(* Logix 5000 project; controller SmartVs_V02 1769-L33ERM rev 32.11; software revision 32.01 *)

TASK MainTask (continuous, watchdog 500 ms) : MainProgram

MODULES
   Local : 1769-L33ERM (Compact 0, rev 32.11)
END_MODULES

TYPE SKT_Accept_Response :
STRUCT
   Instance : DINT;
   Addr : SKT_Address;
END_STRUCT
END_TYPE

TYPE SKT_Address :
STRUCT
   Family : INT;   // Address Family Must be 2
   Port : INT;   // Port Number
   Addr : SINT[4];   // IP Address
END_STRUCT
END_TYPE

TYPE SKT_Create_Parameters :
STRUCT
   Type : DINT;   // 1 - TCP 2- UPD
   Addr : SKT_Address;
END_STRUCT
END_TYPE

TYPE SKT_DATA_CLIENT :
STRUCT
   Timeout : DINT;
   Create_Source : SKT_Create_Parameters;
   Instance : DINT;
   Connect_Source : SKT_OpenConnection_Parameters;
   Read_Source : SKT_Read_Parameters;
   Read_Response : SKT_Read_Response;
   Write_Source : SKT_Write_Parameters;
   Write_SizeSent : DINT;
END_STRUCT
END_TYPE

TYPE SKT_DATA_SERVER :
STRUCT
   Timeout : DINT;
   Create_Source : SKT_Create_Parameters;
   Accept_Socket_Instance : DINT;
   Accept_Timeout : DINT;
   Accept_Response : SKT_Accept_Response;
   Read_Source : SKT_Read_Parameters;
   Read_Response : SKT_Read_Response;
   Write_Source : SKT_Write_Parameters;
   Write_SizeSent : DINT;
   Server_Socket_Instance : DINT;
END_STRUCT
END_TYPE

TYPE SKT_DATA_UDP :
STRUCT
   Timeout : DINT;
   Create_Source : SKT_Create_Parameters;
   Connect_Source : SKT_OpenConnection_Parameters;
   Read_Source : SKT_Read_Parameters;
   Write_Source : SKT_Write_Parameters;
   Instance : DINT;
   Read_Response : SKT_Read_Response;
   Write_SizeSent : DINT;
END_STRUCT
END_TYPE

TYPE SKT_OpenConnection_Parameters :
STRUCT
   Timeout : DINT;
   DestAddr : STRING;
END_STRUCT
END_TYPE

TYPE SKT_Read_Parameters :
STRUCT
   Timeout : DINT;
   BufLen : DINT;
END_STRUCT
END_TYPE

TYPE SKT_Read_Response :
STRUCT
   FromAddr : SKT_Address;
   Buffer : STR_480;
END_STRUCT
END_TYPE

TYPE SKT_Write_Parameters :
STRUCT
   Timeout : DINT;
   ToAddr : SKT_Address;
   Buffer : STR_480;
END_STRUCT
END_TYPE

TYPE STR_480 :   // string type
STRUCT
   LEN : DINT;
   DATA : SINT[480];
END_STRUCT
END_TYPE

TYPE UDT_SmartVs :
STRUCT
   i_xEnable : BOOL;   // Enable Socket Creation and Connection
   i_xWrite : BOOL;   // Write Data Rq
   iq_xResetFB : BOOL;   // Delete all open Sockets
   i_xChangeJob : BOOL;   // Load Job-a number between 1-24
   i_sJobData : STRING;   // Job Data
   o_xEnabled : BOOL;   // Socket created and connected
   o_sJobResult : STRING;   // Job Result String (Done/Fail)
   o_iErrorCode : INT;   // FB Error code
   iState : INT;
   i_iJobData : INT;   // Number of job to load
   sFeedback : STRING;   // Feedback string-from server to client
   sFormatData : STRING;   // Number of job in String Format
   o_xError : BOOL;   // Error
   o_iError : INT;   // FB diagnostic Error code
   diStringlen : DINT;   // String lenght according to the format number
END_STRUCT
END_TYPE

ADD_ON_INSTRUCTION SKT_AOI_TCP_CLIENT   (* revision 1.0, ExecutePrescan *)
VAR_IN_OUT
   Client_Data : SKT_DATA_CLIENT; {required}   // This tags holds all the data used by the messages
END_VAR
VAR_INPUT
   Enable_Socket : BOOL; {visible}   // Set by user to enable or disable socket
   Stop_On_Error : BOOL; {visible}   // If any message errors, then delete socket and stop
END_VAR
VAR_IN_OUT
   Create_MSG : MESSAGE; {required}   // Create socket
   Connect_MSG : MESSAGE; {required}   // Connect socket to server.
   Read_MSG : MESSAGE; {required}   // Message to tell socket to return any data it has recieved
   Write_MSG : MESSAGE; {required}   // Write socket message
   Delete_MSG : MESSAGE; {required}   // Delete socket
END_VAR
VAR_OUTPUT
   ENABLED : BOOL; {access Read Only, visible}   // Socket not currently open
   CONNECTING : BOOL; {access Read Only, visible}   // Trying to connect to Server.
   OPEN : BOOL; {access Read Only, visible}   // Socket connection Open
   READ : BOOL; {access Read Only, visible}   // New Data Ready - Set by AOI when a string is received, cleared by user to acknowledge
   WRITE : BOOL; {access Read Only, visible}   // Set this bit to Write Data
   ERROR : BOOL; {access Read Only, visible}   // A message had an Error
END_VAR
VAR
   lastport : DINT; {access None}
   xEnable : DINT; {access None}
   xWrite : DINT; {access None}
   xRead : DINT; {access None}
   State : DINT := 60;   // Current state
END_VAR

ROUTINE Logic   (* ladder *)
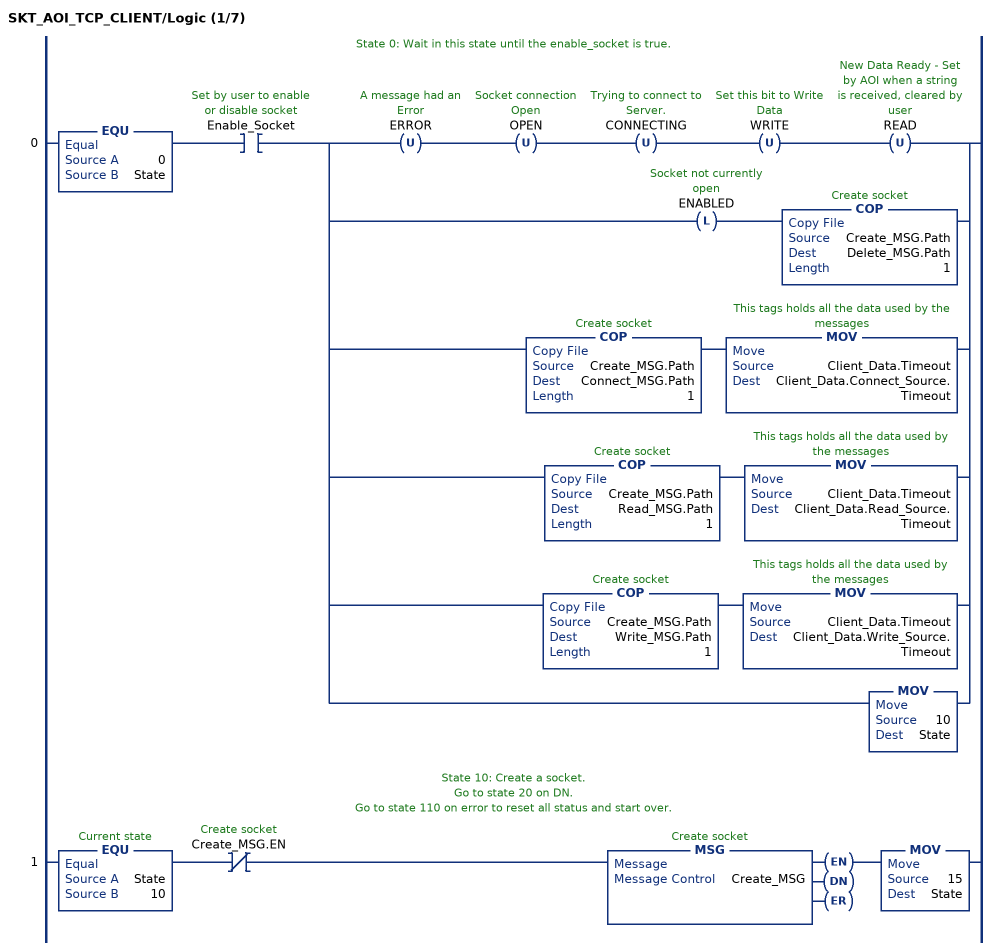
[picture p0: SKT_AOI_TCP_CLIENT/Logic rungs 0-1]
   // State 0: Wait in this state until the enable_socket is true.
   0: EQU(0,State)XIC(Enable_Socket)[OTU(ERROR) OTU(OPEN) OTU(CONNECTING) OTU(WRITE) OTU(READ) ,OTL(ENABLED) COP(Create_MSG.Path,Delete_MSG.Path,1) ,COP(Create_MSG.Path,Connect_MSG.Path,1) MOV(Client_Data.Timeout,Client_Data.Connect_Source.Timeout) ,COP(Create_MSG.Path,Read_MSG.Path,1) MOV(Client_Data.Timeout,Client_Data.Read_Source.Timeout) ,COP(Create_MSG.Path,Write_MSG.Path,1) MOV(Client_Data.Timeout,Client_Data.Write_Source.Timeout) ,MOV(10,State) ];
   // State 10: Create a socket.
   // Go to state 20 on DN.
   // Go to state 110 on error to reset all status and start over.
   1: EQU(State,10)XIO(Create_MSG.EN)MSG(Create_MSG)MOV(15,State);
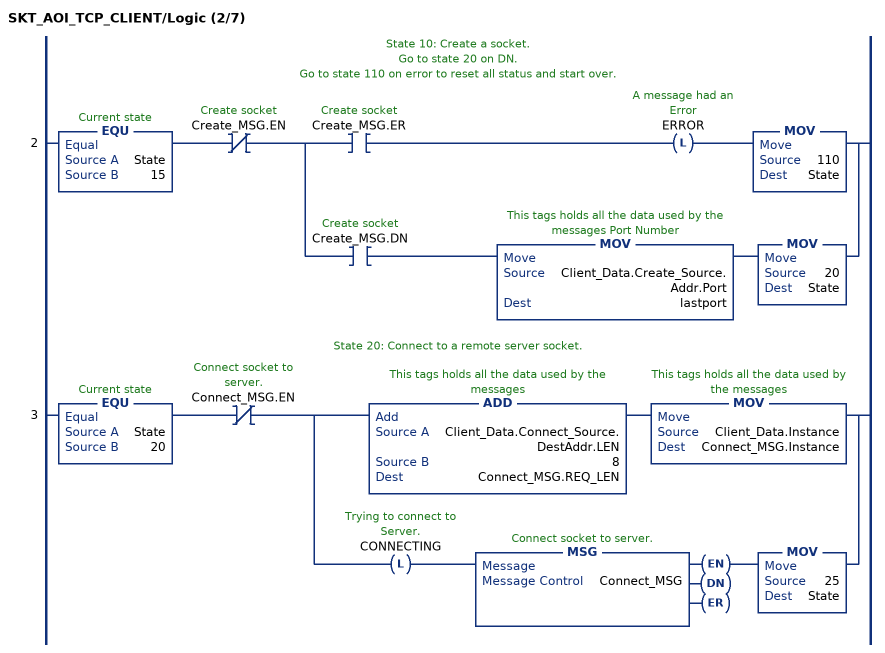
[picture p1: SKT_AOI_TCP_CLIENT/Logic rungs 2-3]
   // State 10: Create a socket.
   // Go to state 20 on DN.
   // Go to state 110 on error to reset all status and start over.
   2: EQU(State,15)XIO(Create_MSG.EN)[XIC(Create_MSG.ER) OTL(ERROR) MOV(110,State) ,XIC(Create_MSG.DN) MOV(Client_Data.Create_Source.Addr.Port,lastport) MOV(20,State) ];
   // State 20: Connect to a remote server socket.
   3: EQU(State,20)XIO(Connect_MSG.EN)[ADD(Client_Data.Connect_Source.DestAddr.LEN,8,Connect_MSG.REQ_LEN) MOV(Client_Data.Instance,Connect_MSG.Instance) ,OTL(CONNECTING) MSG(Connect_MSG) MOV(25,State) ];
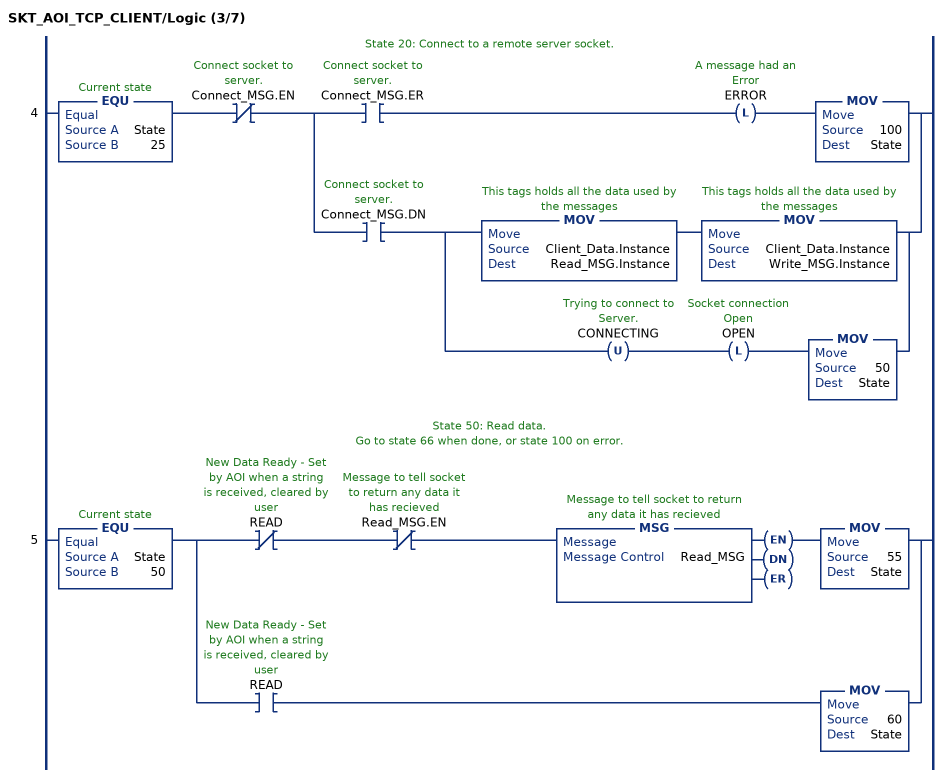
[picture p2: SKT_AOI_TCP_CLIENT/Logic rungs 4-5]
   // State 20: Connect to a remote server socket.
   4: EQU(State,25)XIO(Connect_MSG.EN)[XIC(Connect_MSG.ER) OTL(ERROR) MOV(100,State) ,XIC(Connect_MSG.DN) [MOV(Client_Data.Instance,Read_MSG.Instance) MOV(Client_Data.Instance,Write_MSG.Instance) ,OTU(CONNECTING) OTL(OPEN) MOV(50,State) ] ];
   // State 50: Read data.
   // Go to state 66 when done, or state 100 on error.
   5: EQU(State,50)[XIO(READ) XIO(Read_MSG.EN) MSG(Read_MSG) MOV(55,State) ,XIC(READ) MOV(60,State) ];
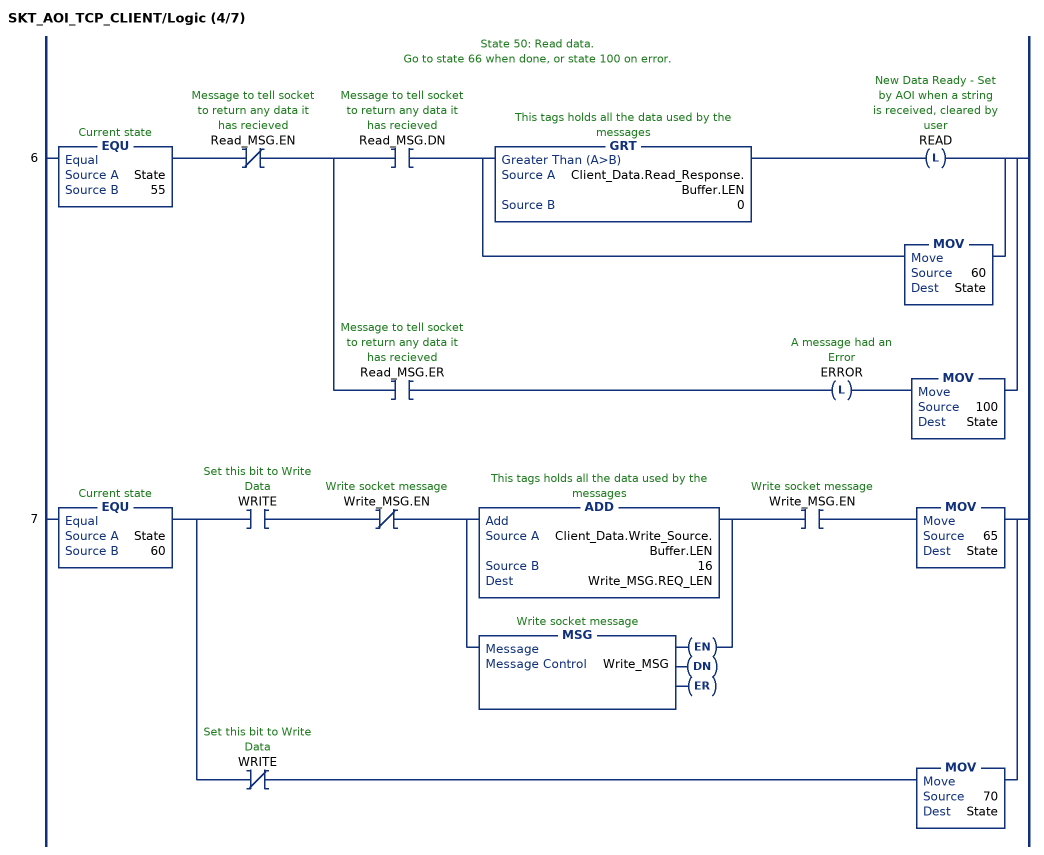
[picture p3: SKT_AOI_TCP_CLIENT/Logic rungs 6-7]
   // State 50: Read data.
   // Go to state 66 when done, or state 100 on error.
   6: EQU(State,55)XIO(Read_MSG.EN)[XIC(Read_MSG.DN) [GRT(Client_Data.Read_Response.Buffer.LEN,0) OTL(READ) ,MOV(60,State) ] ,XIC(Read_MSG.ER) OTL(ERROR) MOV(100,State) ];
   7: EQU(State,60)[XIC(WRITE) XIO(Write_MSG.EN) [ADD(Client_Data.Write_Source.Buffer.LEN,16,Write_MSG.REQ_LEN) ,MSG(Write_MSG) ] XIC(Write_MSG.EN) MOV(65,State) ,XIO(WRITE) MOV(70,State) ];
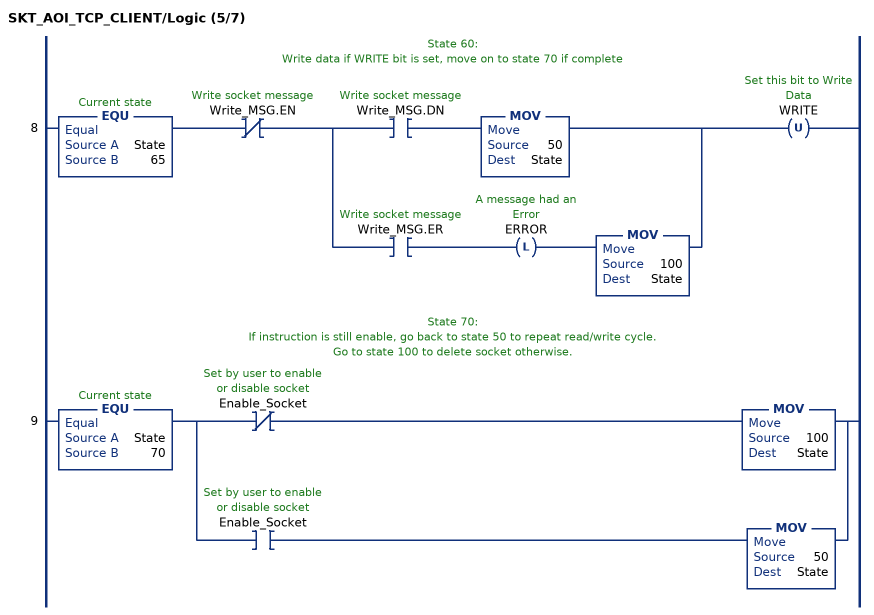
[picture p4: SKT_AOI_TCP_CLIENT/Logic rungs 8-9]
   // State 60:
   // Write data if WRITE bit is set, move on to state 70 if complete
   8: EQU(State,65)XIO(Write_MSG.EN)[XIC(Write_MSG.DN) MOV(50,State) ,XIC(Write_MSG.ER) OTL(ERROR) MOV(100,State) ]OTU(WRITE);
   // State 70:
   // If instruction is still enable, go back to state 50 to repeat read/write cycle.
   // Go to state 100 to delete socket otherwise.
   9: EQU(State,70)[XIO(Enable_Socket) MOV(100,State) ,XIC(Enable_Socket) MOV(50,State) ];
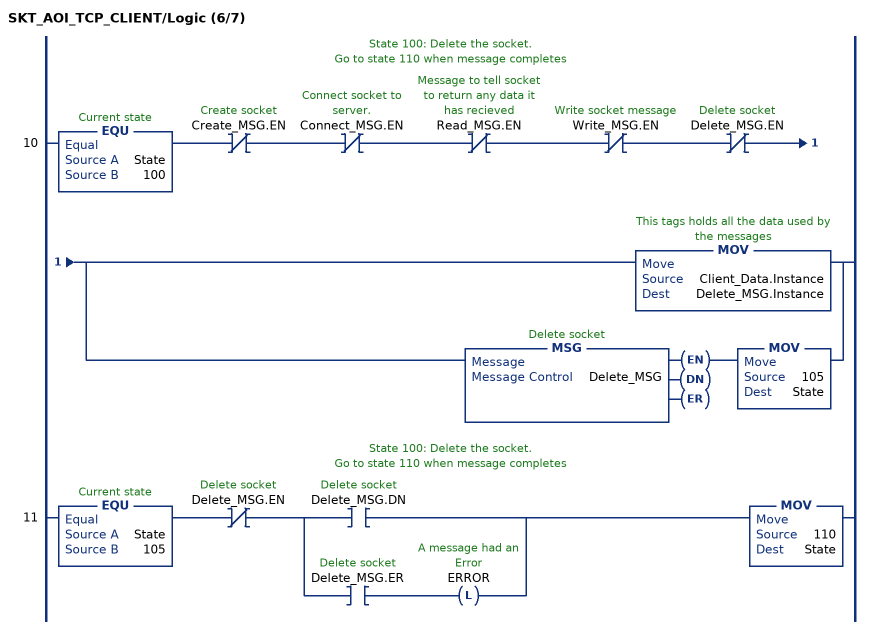
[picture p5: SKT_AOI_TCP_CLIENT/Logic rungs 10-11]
   // State 100: Delete the socket.
   // Go to state 110 when message completes
   10: EQU(State,100)XIO(Create_MSG.EN)XIO(Connect_MSG.EN)XIO(Read_MSG.EN)XIO(Write_MSG.EN)XIO(Delete_MSG.EN)[MOV(Client_Data.Instance,Delete_MSG.Instance) ,MSG(Delete_MSG) MOV(105,State) ];
   // State 100: Delete the socket.
   // Go to state 110 when message completes
   11: EQU(State,105)XIO(Delete_MSG.EN)[XIC(Delete_MSG.DN) ,XIC(Delete_MSG.ER) OTL(ERROR) ]MOV(110,State);
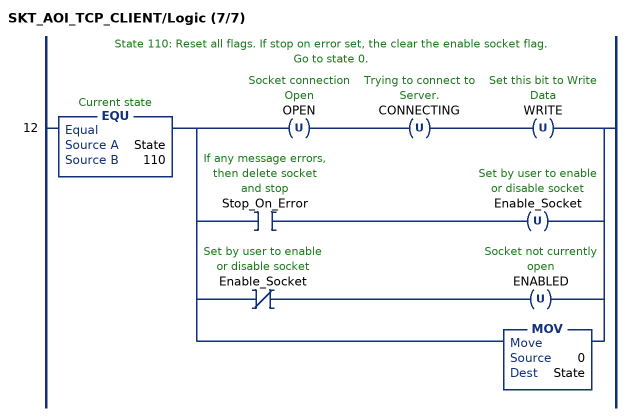
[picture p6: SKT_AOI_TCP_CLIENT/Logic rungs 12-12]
   // State 110: Reset all flags. If stop on error set, the clear the enable socket flag.
   // Go to state 0.
   12: EQU(State,110)[OTU(OPEN) OTU(CONNECTING) OTU(WRITE) ,XIC(Stop_On_Error) OTU(Enable_Socket) ,XIO(Enable_Socket) OTU(ENABLED) ,MOV(0,State) ];
END_ROUTINE

ROUTINE Prescan   (* ladder *)
// Prescan
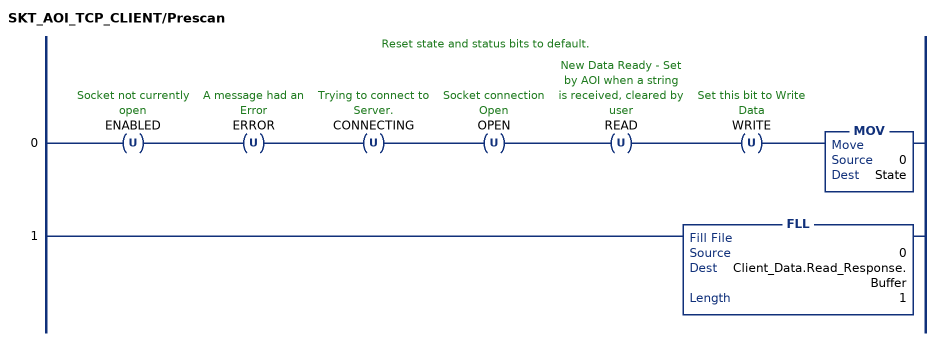
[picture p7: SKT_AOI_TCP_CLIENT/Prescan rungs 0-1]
   // Reset state and status bits to default.
   0: OTU(ENABLED)OTU(ERROR)OTU(CONNECTING)OTU(OPEN)OTU(READ)OTU(WRITE)MOV(0,State);
   1: FLL(0,Client_Data.Read_Response.Buffer,1);
END_ROUTINE
END_ADD_ON_INSTRUCTION

ADD_ON_INSTRUCTION SKT_AOI_TCP_SERVER   (* revision 1.0, ExecutePrescan *)
VAR_IN_OUT
   Server_Data : SKT_DATA_SERVER; {required}   // This tag is used to hold source and dest tags of all socket messages.
        .Read_Response.Buffer.LEN   // Tag used to hold data for messages
END_VAR
VAR_INPUT
   Enable_Socket : BOOL; {visible}   // Set by user to enable or disable socket
   Stop_on_Error : BOOL; {visible}   // Stop on any socket errors
END_VAR
VAR_IN_OUT
   Create_MSG : MESSAGE; {required}   // Create socket
   Accept_MSG : MESSAGE; {required}   // Listen for incoming connection.
   Read_MSG : MESSAGE; {required}   // Read Socket Message
   Write_MSG : MESSAGE; {required}   // Write socket message
   Delete_MSG : MESSAGE; {required}   // Delete socket
END_VAR
VAR_OUTPUT
   ENABLED : BOOL; {access Read Only, visible}
   LISTENING : BOOL; {access Read Only, visible}   // Socket is listening for incoming connection
   OPEN : BOOL; {access Read Only, visible}   // Socket Connection Open
   READ : BOOL; {access Read Only, visible}   // Data in Read buffer
   WRITE : BOOL; {access Read Only, visible}   // Set to send data.
   ERROR : BOOL; {access Read Only, visible}   // At least one message has an error
END_VAR
VAR
   State : DINT := 20;   // Current state
   DELETE_Socket : BOOL; {access None}
   DELETE_Running : BOOL; {access None}
END_VAR

ROUTINE Logic   (* ladder *)
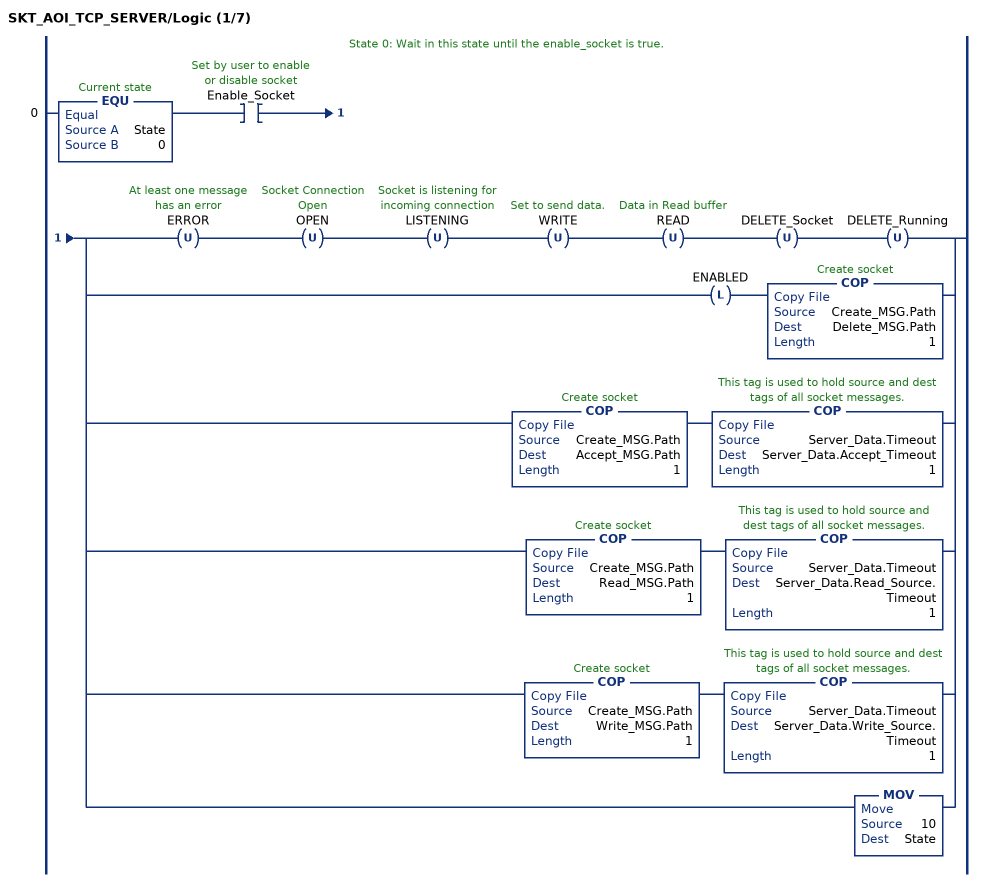
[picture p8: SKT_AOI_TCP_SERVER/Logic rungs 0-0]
   // State 0: Wait in this state until the enable_socket is true.
   0: EQU(State,0)XIC(Enable_Socket)[OTU(ERROR) OTU(OPEN) OTU(LISTENING) OTU(WRITE) OTU(READ) OTU(DELETE_Socket) OTU(DELETE_Running) ,OTL(ENABLED) COP(Create_MSG.Path,Delete_MSG.Path,1) ,COP(Create_MSG.Path,Accept_MSG.Path,1) COP(Server_Data.Timeout,Server_Data.Accept_Timeout,1) ,COP(Create_MSG.Path,Read_MSG.Path,1) COP(Server_Data.Timeout,Server_Data.Read_Source.Timeout,1) ,COP(Create_MSG.Path,Write_MSG.Path,1) COP(Server_Data.Timeout,Server_Data.Write_Source.Timeout,1) ,MOV(10,State) ];
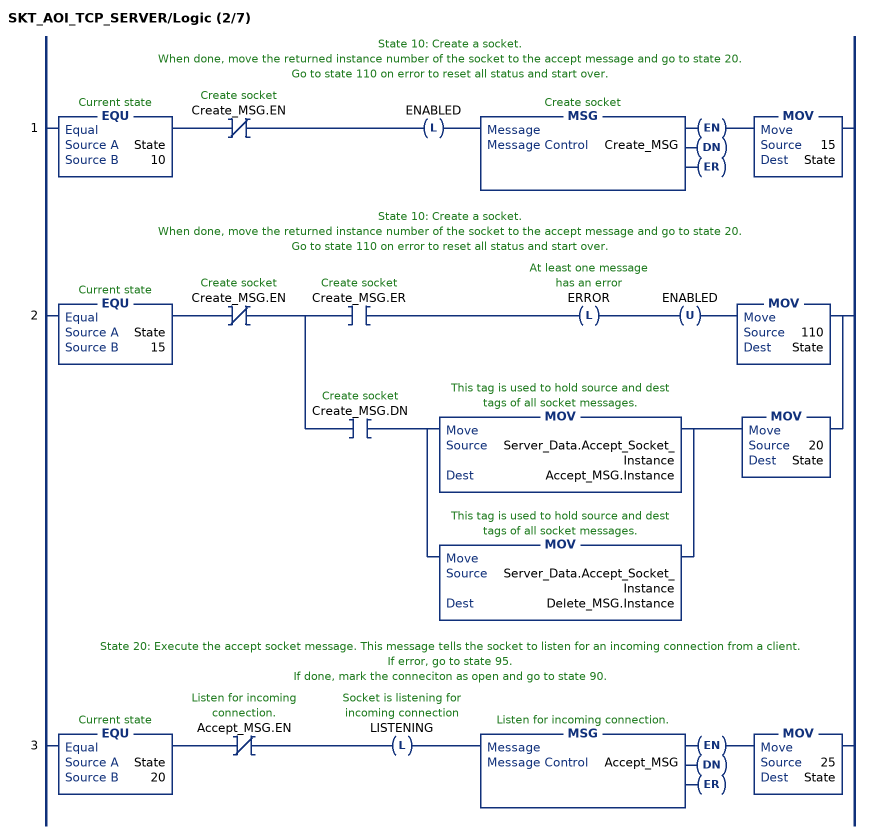
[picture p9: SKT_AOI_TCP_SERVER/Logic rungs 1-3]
   // State 10: Create a socket.
   // When done, move the returned instance number of the socket to the accept message and go to state 20.
   // Go to state 110 on error to reset all status and start over.
   1: EQU(State,10)XIO(Create_MSG.EN)OTL(ENABLED)MSG(Create_MSG)MOV(15,State);
   // State 10: Create a socket.
   // When done, move the returned instance number of the socket to the accept message and go to state 20.
   // Go to state 110 on error to reset all status and start over.
   2: EQU(State,15)XIO(Create_MSG.EN)[XIC(Create_MSG.ER) OTL(ERROR) OTU(ENABLED) MOV(110,State) ,XIC(Create_MSG.DN) [MOV(Server_Data.Accept_Socket_Instance,Accept_MSG.Instance) ,MOV(Server_Data.Accept_Socket_Instance,Delete_MSG.Instance) ] MOV(20,State) ];
   // State 20: Execute the accept socket message. This message tells the socket to listen for an incoming connection from a client.
   // If error, go to state 95.
   // If done, mark the conneciton as open and go to state 90.
   3: EQU(State,20)XIO(Accept_MSG.EN)OTL(LISTENING)MSG(Accept_MSG)MOV(25,State);
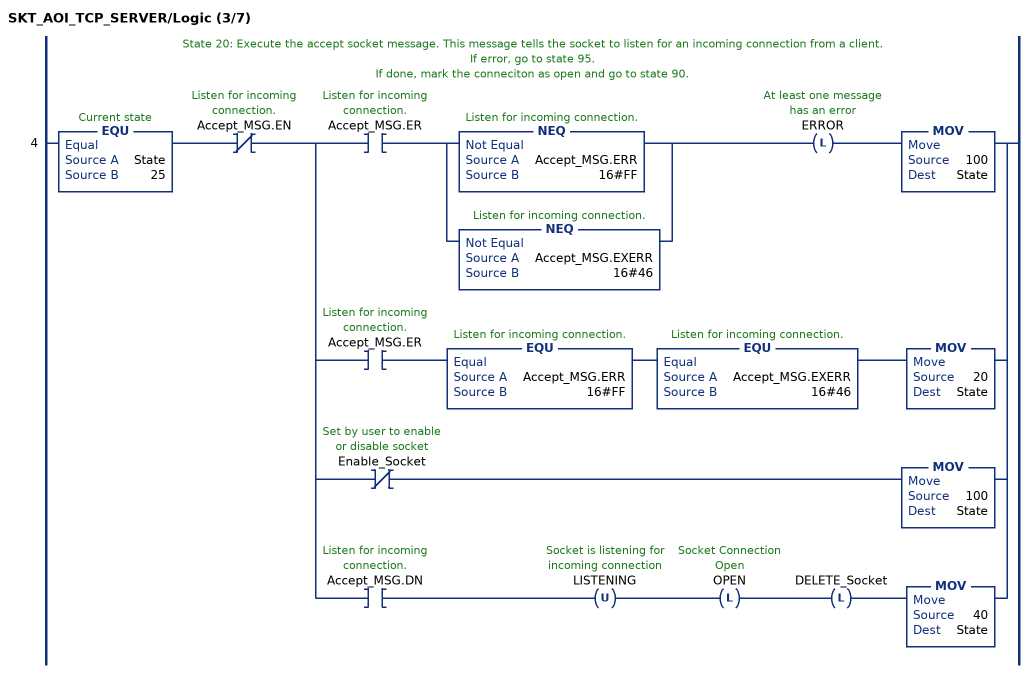
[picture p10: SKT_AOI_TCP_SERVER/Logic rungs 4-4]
   // State 20: Execute the accept socket message. This message tells the socket to listen for an incoming connection from a client.
   // If error, go to state 95.
   // If done, mark the conneciton as open and go to state 90.
   4: EQU(State,25)XIO(Accept_MSG.EN)[XIC(Accept_MSG.ER) [NEQ(Accept_MSG.ERR,16#FF) ,NEQ(Accept_MSG.EXERR,16#46) ] OTL(ERROR) MOV(100,State) ,XIC(Accept_MSG.ER) EQU(Accept_MSG.ERR,16#FF) EQU(Accept_MSG.EXERR,16#46) MOV(20,State) ,XIO(Enable_Socket) MOV(100,State) ,XIC(Accept_MSG.DN) OTU(LISTENING) OTL(OPEN) OTL(DELETE_Socket) MOV(40,State) ];
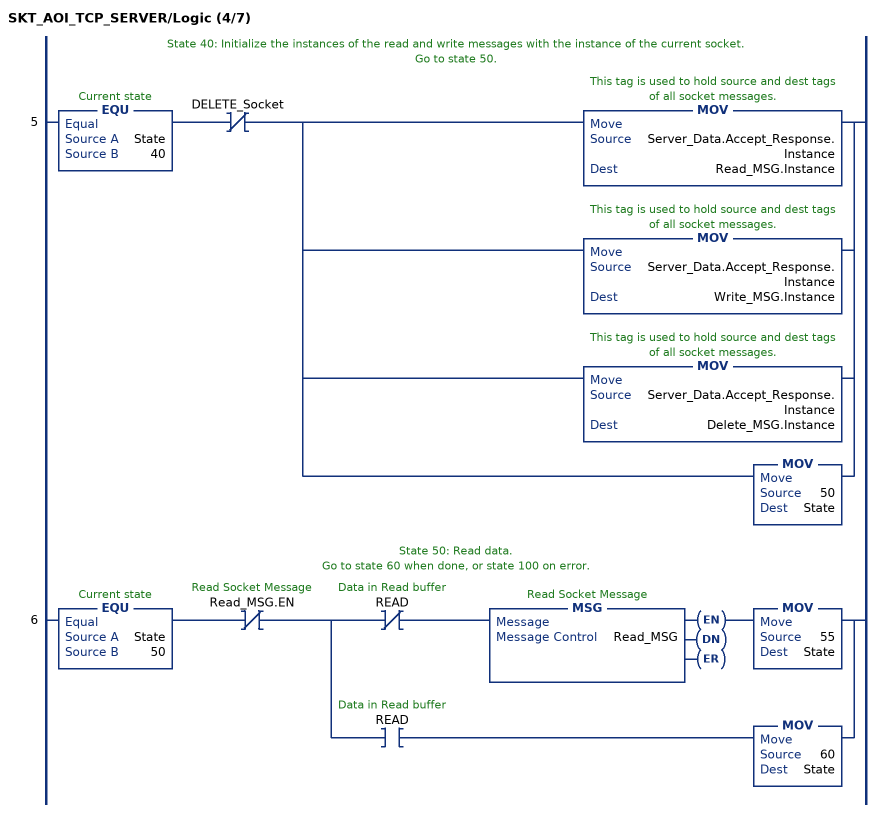
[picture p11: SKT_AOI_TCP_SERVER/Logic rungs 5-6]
   // State 40: Initialize the instances of the read and write messages with the instance of the current socket.
   // Go to state 50.
   5: EQU(State,40)XIO(DELETE_Socket)[MOV(Server_Data.Accept_Response.Instance,Read_MSG.Instance) ,MOV(Server_Data.Accept_Response.Instance,Write_MSG.Instance) ,MOV(Server_Data.Accept_Response.Instance,Delete_MSG.Instance) ,MOV(50,State) ];
   // State 50: Read data.
   // Go to state 60 when done, or state 100 on error.
   6: EQU(State,50)XIO(Read_MSG.EN)[XIO(READ) MSG(Read_MSG) MOV(55,State) ,XIC(READ) MOV(60,State) ];
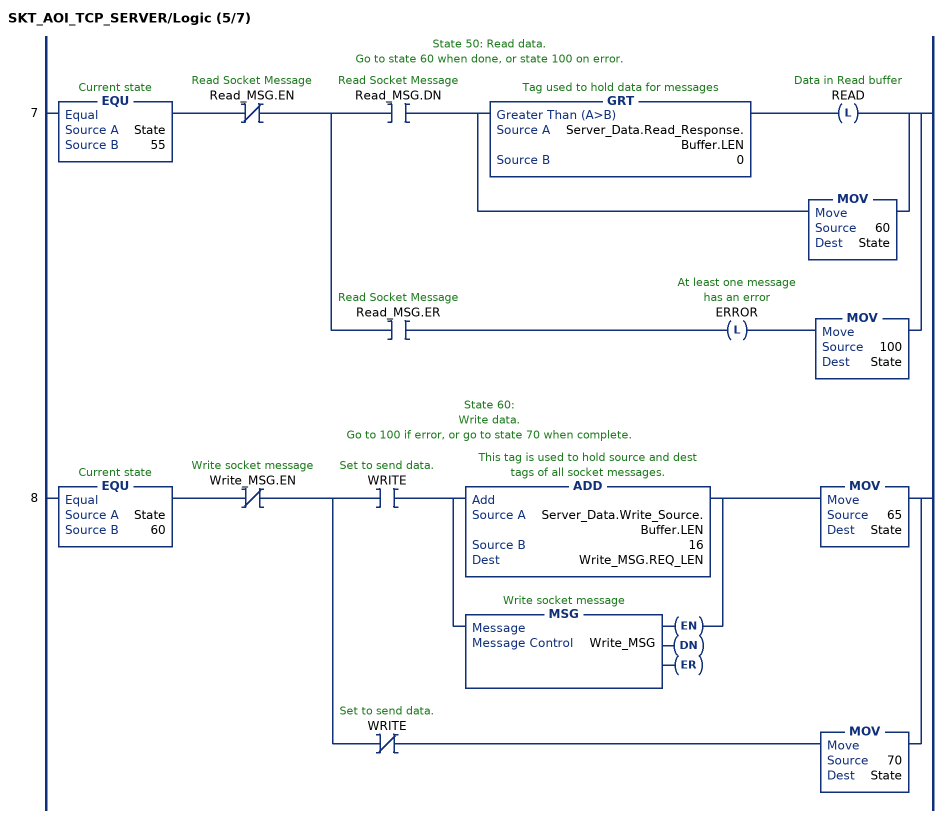
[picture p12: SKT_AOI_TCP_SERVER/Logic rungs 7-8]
   // State 50: Read data.
   // Go to state 60 when done, or state 100 on error.
   7: EQU(State,55)XIO(Read_MSG.EN)[XIC(Read_MSG.DN) [GRT(Server_Data.Read_Response.Buffer.LEN,0) OTL(READ) ,MOV(60,State) ] ,XIC(Read_MSG.ER) OTL(ERROR) MOV(100,State) ];
   // State 60:
   // Write data.
   // Go to 100 if error, or go to state 70 when complete.
   8: EQU(State,60)XIO(Write_MSG.EN)[XIC(WRITE) [ADD(Server_Data.Write_Source.Buffer.LEN,16,Write_MSG.REQ_LEN) ,MSG(Write_MSG) ] MOV(65,State) ,XIO(WRITE) MOV(70,State) ];
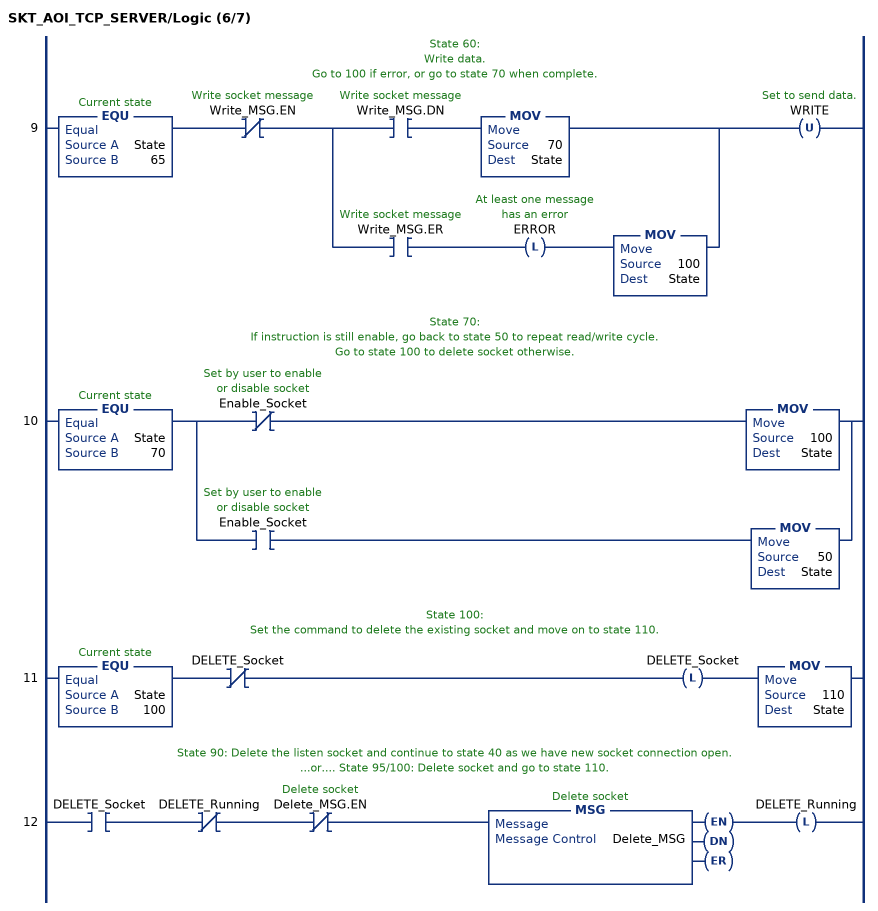
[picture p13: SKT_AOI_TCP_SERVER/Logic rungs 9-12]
   // State 60:
   // Write data.
   // Go to 100 if error, or go to state 70 when complete.
   9: EQU(State,65)XIO(Write_MSG.EN)[XIC(Write_MSG.DN) MOV(70,State) ,XIC(Write_MSG.ER) OTL(ERROR) MOV(100,State) ]OTU(WRITE);
   // State 70:
   // If instruction is still enable, go back to state 50 to repeat read/write cycle.
   // Go to state 100 to delete socket otherwise.
   10: EQU(State,70)[XIO(Enable_Socket) MOV(100,State) ,XIC(Enable_Socket) MOV(50,State) ];
   // State 100:
   // Set the command to delete the existing socket and move on to state 110.
   11: EQU(State,100)XIO(DELETE_Socket)OTL(DELETE_Socket)MOV(110,State);
   // State 90: Delete the listen socket and continue to state 40 as we have new socket connection open.
   // ...or.... State 95/100: Delete socket and go to state 110.
   12: XIC(DELETE_Socket)XIO(DELETE_Running)XIO(Delete_MSG.EN)MSG(Delete_MSG)OTL(DELETE_Running);
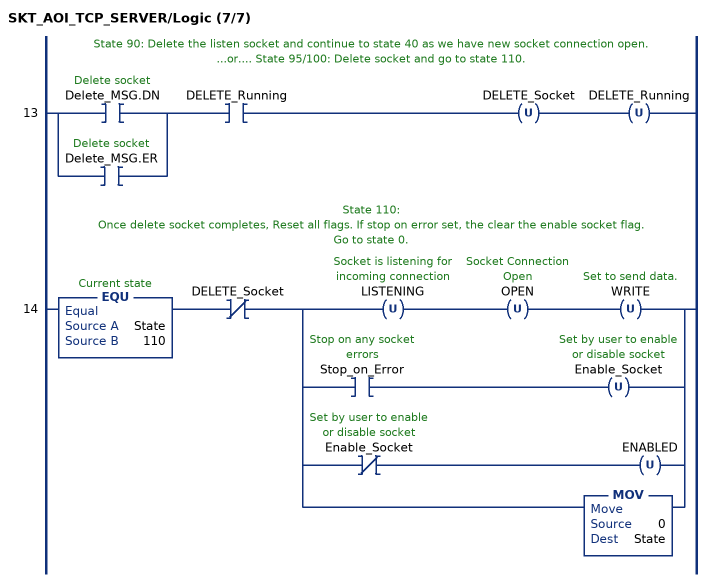
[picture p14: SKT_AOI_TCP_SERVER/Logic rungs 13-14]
   // State 90: Delete the listen socket and continue to state 40 as we have new socket connection open.
   // ...or.... State 95/100: Delete socket and go to state 110.
   13: [XIC(Delete_MSG.DN) ,XIC(Delete_MSG.ER) ]XIC(DELETE_Running)OTU(DELETE_Socket)OTU(DELETE_Running);
   // State 110:
   // Once delete socket completes, Reset all flags. If stop on error set, the clear the enable socket flag.
   // Go to state 0.
   14: EQU(State,110)XIO(DELETE_Socket)[OTU(LISTENING) OTU(OPEN) OTU(WRITE) ,XIC(Stop_on_Error) OTU(Enable_Socket) ,XIO(Enable_Socket) OTU(ENABLED) ,MOV(0,State) ];
END_ROUTINE

ROUTINE Prescan   (* ladder *)
// Prescan
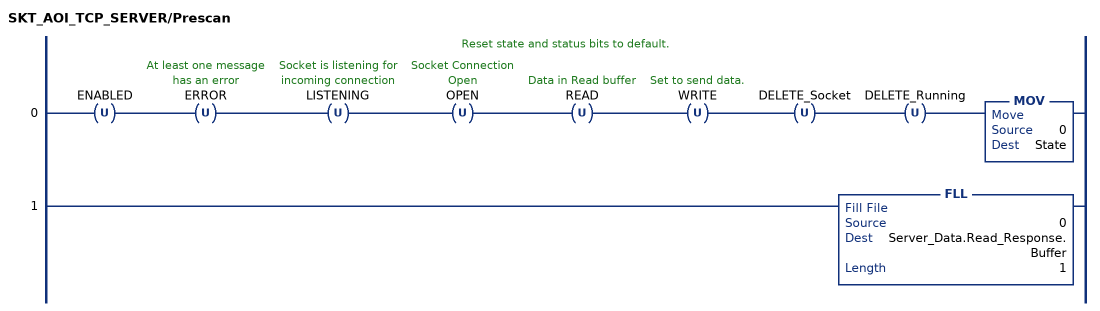
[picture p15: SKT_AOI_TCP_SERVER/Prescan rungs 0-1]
   // Reset state and status bits to default.
   0: OTU(ENABLED)OTU(ERROR)OTU(LISTENING)OTU(OPEN)OTU(READ)OTU(WRITE)OTU(DELETE_Socket)OTU(DELETE_Running)MOV(0,State);
   1: FLL(0,Server_Data.Read_Response.Buffer,1);
END_ROUTINE
END_ADD_ON_INSTRUCTION

ADD_ON_INSTRUCTION SKT_AOI_UDP   (* revision 1.0, ExecutePrescan *)
VAR_IN_OUT
   UDP_Data : SKT_DATA_UDP; {required}   // Holds all data sent and recieved by message instructions
END_VAR
VAR_INPUT
   Enable_Socket : BOOL; {visible}   // Set by user to enable or disable socket
   Stop_on_Error : BOOL; {visible}   // If any message errors, then stop and close the socket.
END_VAR
VAR_IN_OUT
   Create_MSG : MESSAGE; {required}   // Create socket
   Connect_MSG : MESSAGE; {required}
   Read_MSG : MESSAGE; {required}   // Read data from Socket
   Write_MSG : MESSAGE; {required}   // Write socket message
   Delete_MSG : MESSAGE; {required}   // Delete socket
END_VAR
VAR_OUTPUT
   ENABLED : BOOL; {access Read Only, visible}
   OPEN : BOOL; {access Read Only, visible}   // The Socket is Open
   READ : BOOL; {access Read Only, visible}   // New data in read buffer.
   WRITE : BOOL; {access Read Only, visible}   // Set bit to write data.
   ERROR : BOOL; {access Read Only, visible}   // Set if any message has an error.
END_VAR
VAR
   State : DINT;   // Current state
END_VAR

ROUTINE Logic   (* ladder *)
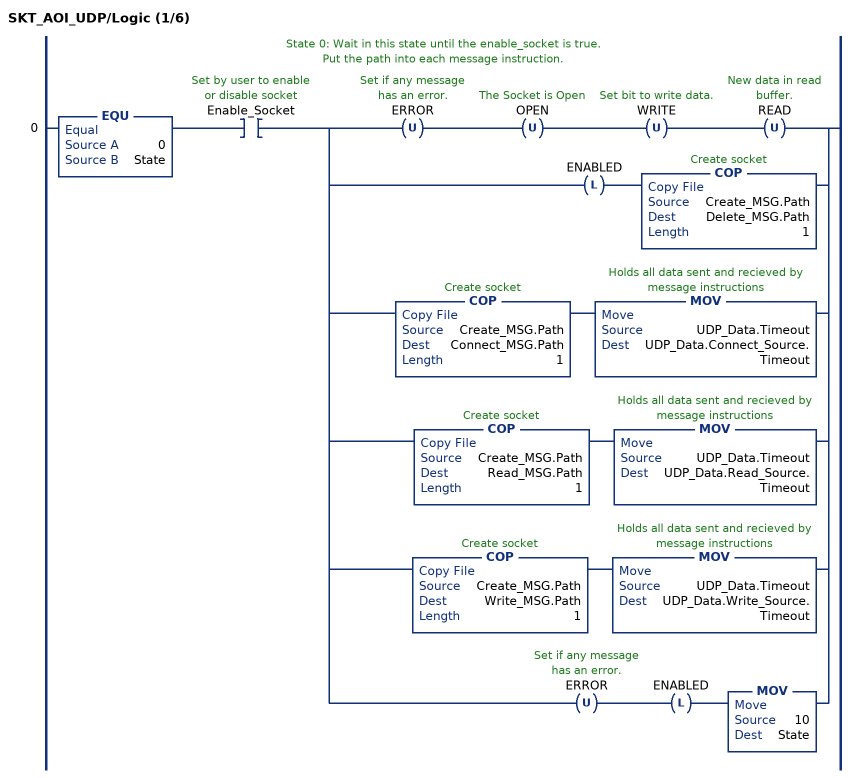
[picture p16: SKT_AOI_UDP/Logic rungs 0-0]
   // State 0: Wait in this state until the enable_socket is true.
   // Put the path into each message instruction.
   0: EQU(0,State)XIC(Enable_Socket)[OTU(ERROR) OTU(OPEN) OTU(WRITE) OTU(READ) ,OTL(ENABLED) COP(Create_MSG.Path,Delete_MSG.Path,1) ,COP(Create_MSG.Path,Connect_MSG.Path,1) MOV(UDP_Data.Timeout,UDP_Data.Connect_Source.Timeout) ,COP(Create_MSG.Path,Read_MSG.Path,1) MOV(UDP_Data.Timeout,UDP_Data.Read_Source.Timeout) ,COP(Create_MSG.Path,Write_MSG.Path,1) MOV(UDP_Data.Timeout,UDP_Data.Write_Source.Timeout) ,OTU(ERROR) OTL(ENABLED) MOV(10,State) ];
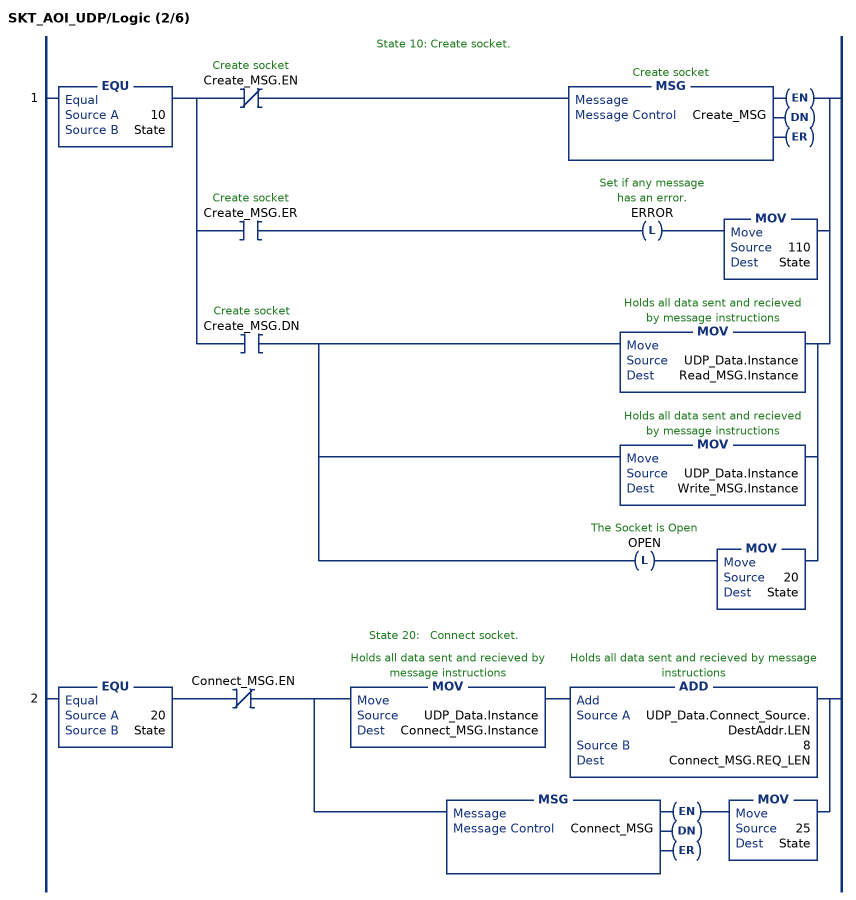
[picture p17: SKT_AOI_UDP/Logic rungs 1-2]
   // State 10: Create socket.
   1: EQU(10,State)[XIO(Create_MSG.EN) MSG(Create_MSG) ,XIC(Create_MSG.ER) OTL(ERROR) MOV(110,State) ,XIC(Create_MSG.DN) [MOV(UDP_Data.Instance,Read_MSG.Instance) ,MOV(UDP_Data.Instance,Write_MSG.Instance) ,OTL(OPEN) MOV(20,State) ] ];
   // State 20:   Connect socket.
   2: EQU(20,State)XIO(Connect_MSG.EN)[MOV(UDP_Data.Instance,Connect_MSG.Instance) ADD(UDP_Data.Connect_Source.DestAddr.LEN,8,Connect_MSG.REQ_LEN) ,MSG(Connect_MSG) MOV(25,State) ];
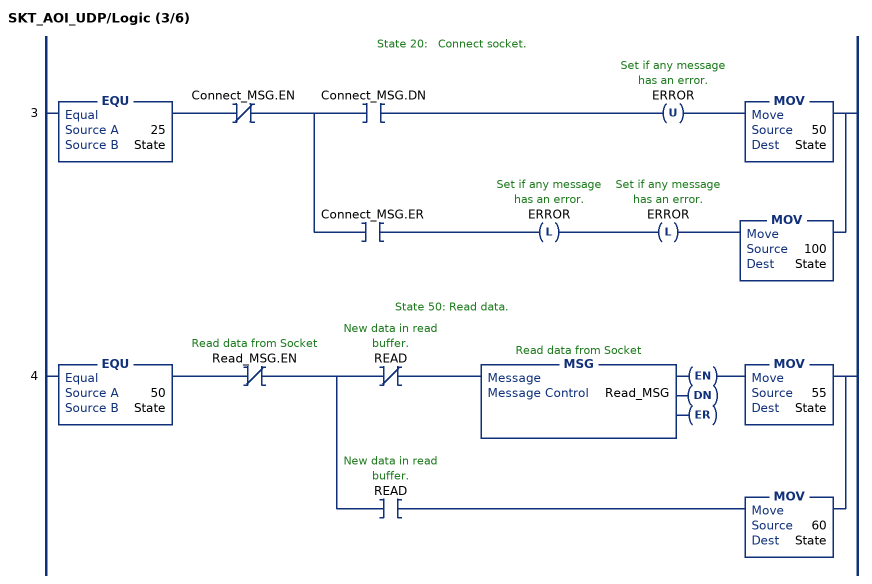
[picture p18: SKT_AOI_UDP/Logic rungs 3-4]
   // State 20:   Connect socket.
   3: EQU(25,State)XIO(Connect_MSG.EN)[XIC(Connect_MSG.DN) OTU(ERROR) MOV(50,State) ,XIC(Connect_MSG.ER) OTL(ERROR) OTL(ERROR) MOV(100,State) ];
   // State 50: Read data.
   4: EQU(50,State)XIO(Read_MSG.EN)[XIO(READ) MSG(Read_MSG) MOV(55,State) ,XIC(READ) MOV(60,State) ];
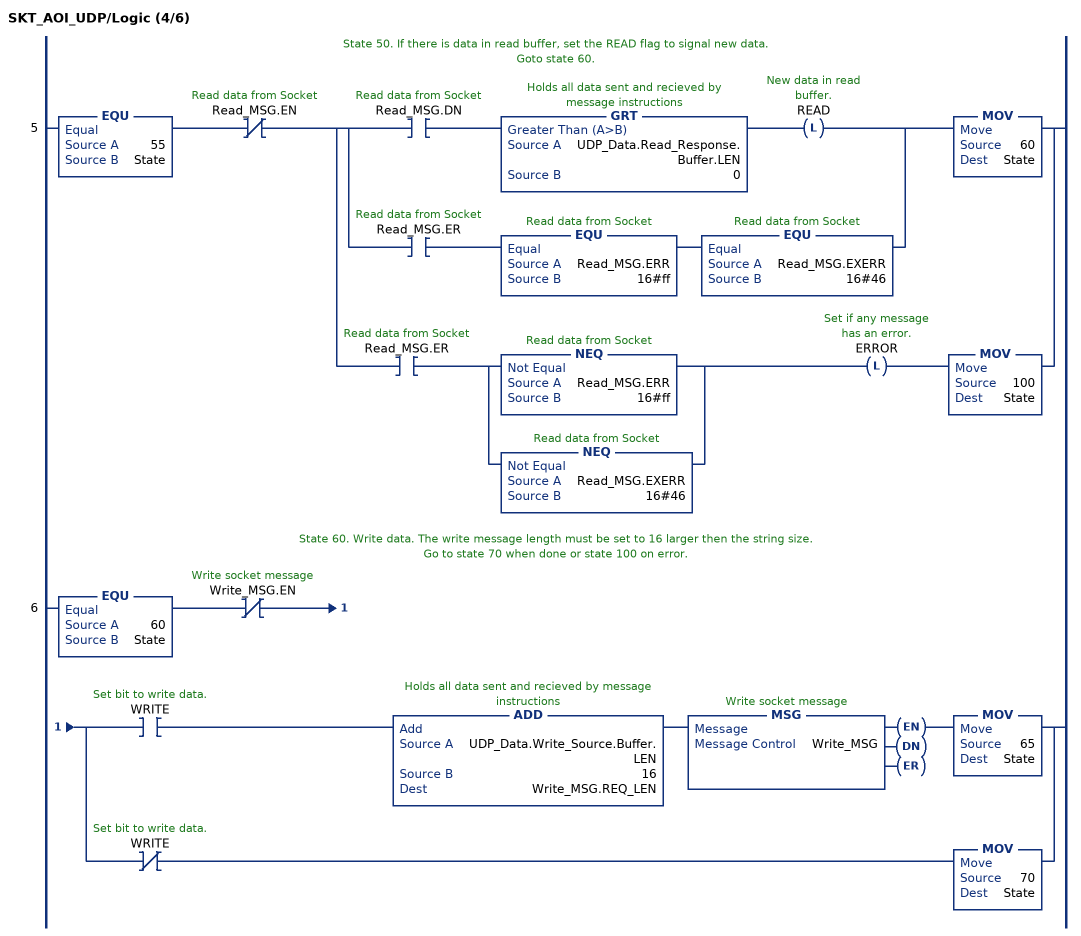
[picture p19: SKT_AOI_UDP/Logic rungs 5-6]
   // State 50. If there is data in read buffer, set the READ flag to signal new data.
   // Goto state 60.
   5: EQU(55,State)XIO(Read_MSG.EN)[[XIC(Read_MSG.DN) GRT(UDP_Data.Read_Response.Buffer.LEN,0) OTL(READ) ,XIC(Read_MSG.ER) EQU(Read_MSG.ERR,16#ff) EQU(Read_MSG.EXERR,16#46) ] MOV(60,State) ,XIC(Read_MSG.ER) [NEQ(Read_MSG.ERR,16#ff) ,NEQ(Read_MSG.EXERR,16#46) ] OTL(ERROR) MOV(100,State) ];
   // State 60. Write data. The write message length must be set to 16 larger then the string size.
   // Go to state 70 when done or state 100 on error.
   6: EQU(60,State)XIO(Write_MSG.EN)[XIC(WRITE) ADD(UDP_Data.Write_Source.Buffer.LEN,16,Write_MSG.REQ_LEN) MSG(Write_MSG) MOV(65,State) ,XIO(WRITE) MOV(70,State) ];
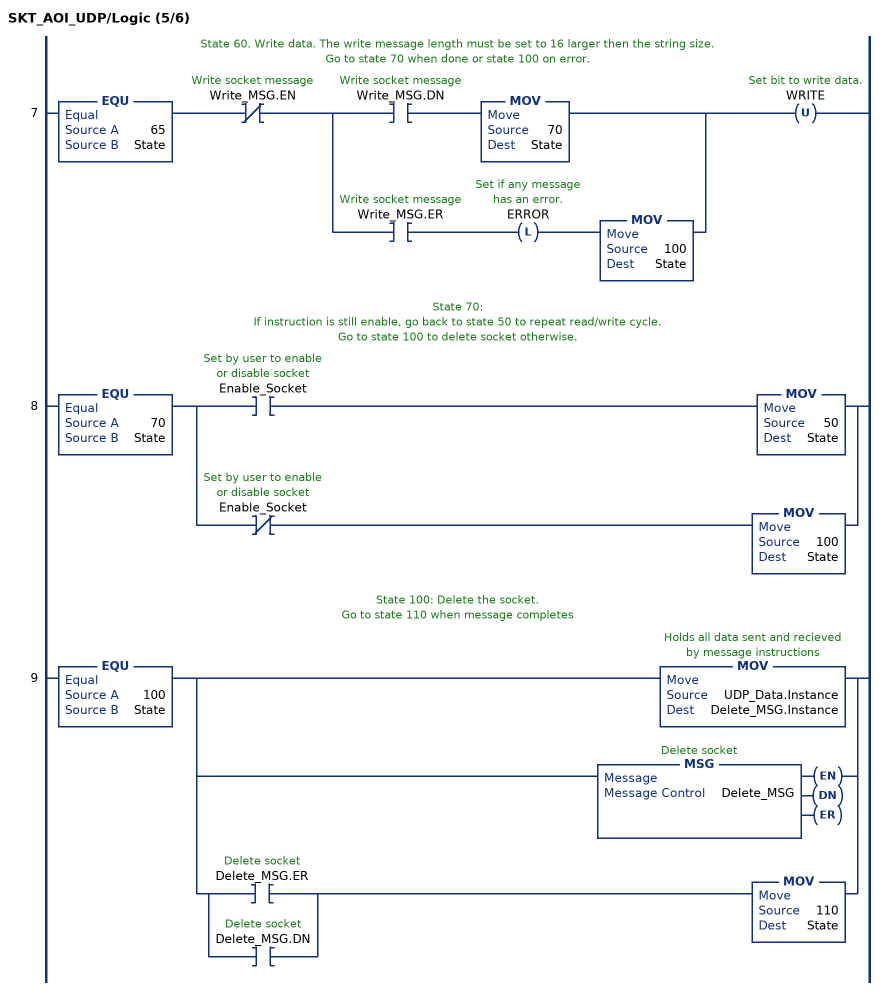
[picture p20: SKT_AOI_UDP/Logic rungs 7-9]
   // State 60. Write data. The write message length must be set to 16 larger then the string size.
   // Go to state 70 when done or state 100 on error.
   7: EQU(65,State)XIO(Write_MSG.EN)[XIC(Write_MSG.DN) MOV(70,State) ,XIC(Write_MSG.ER) OTL(ERROR) MOV(100,State) ]OTU(WRITE);
   // State 70:
   // If instruction is still enable, go back to state 50 to repeat read/write cycle.
   // Go to state 100 to delete socket otherwise.
   8: EQU(70,State)[XIC(Enable_Socket) MOV(50,State) ,XIO(Enable_Socket) MOV(100,State) ];
   // State 100: Delete the socket.
   // Go to state 110 when message completes
   9: EQU(100,State)[MOV(UDP_Data.Instance,Delete_MSG.Instance) ,MSG(Delete_MSG) ,[XIC(Delete_MSG.ER) ,XIC(Delete_MSG.DN) ] MOV(110,State) ];
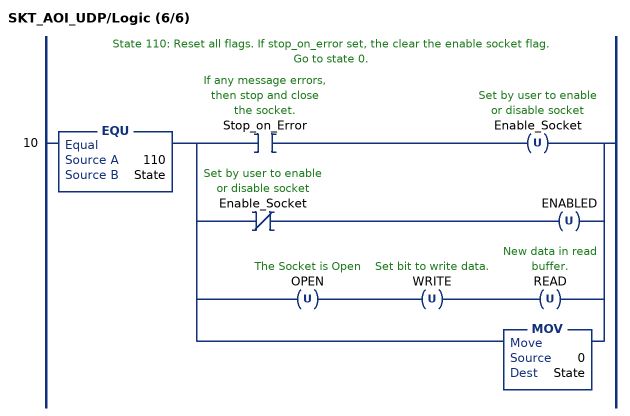
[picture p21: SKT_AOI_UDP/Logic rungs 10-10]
   // State 110: Reset all flags. If stop_on_error set, the clear the enable socket flag.
   // Go to state 0.
   10: EQU(110,State)[XIC(Stop_on_Error) OTU(Enable_Socket) ,XIO(Enable_Socket) OTU(ENABLED) ,OTU(OPEN) OTU(WRITE) OTU(READ) ,MOV(0,State) ];
END_ROUTINE
